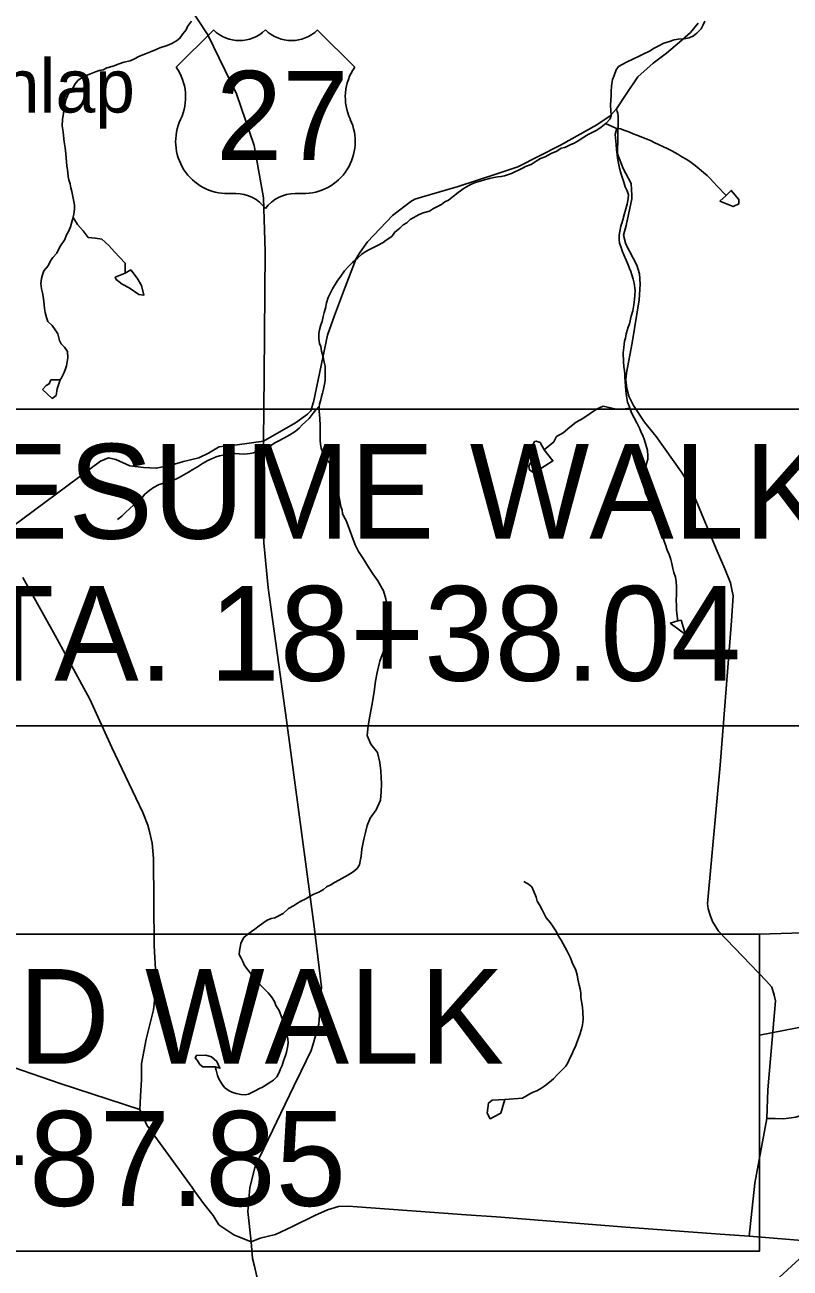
# Model space of a CAD drawing. Extents: x 0 to 69.5, y -4.5 to 22.
# Drawn here: x 3.197 to 4.328, y 18.449 to 20.286 of the extents above; entities that cross this region are included whole.
import ezdxf

# ---------------------------------------------------------------- set-up
doc = ezdxf.new("R2010")
doc.units = 0
for name, color, linetype in [('GM_X_County_Road', 7, 'Continuous'), ('GM_X_Interstate_Route', 7, 'Continuous'), ('GM_X_Minor_Lake', 7, 'Continuous'), ('GM_X_Minor_River', 7, 'Continuous'), ('GM_X_Township_Subdivision', 7, 'Continuous'), ('GM_X_Unincorporated_Text', 7, 'Continuous'), ('GM_X_US_Location', 7, 'Continuous'), ('GM_X_US_Route', 7, 'Continuous'), ('GM_X_US_Shield', 7, 'Continuous'), ('RD_P_Text', 7, 'Continuous'), ('SH_Masking', 7, 'Continuous')]:
    doc.layers.add(name, color=color, linetype=linetype)

msp = doc.modelspace()

# ---------------------------------------------------------------- linework, layer by layer
at = {"layer": 'GM_X_County_Road'}
for points in [[(3.6227, 19.7258), (3.6227, 19.726), (3.6236, 19.7286), (3.6444, 19.8276), (3.6547, 19.8565), (3.6676, 19.8922), (3.6865, 19.941), (3.6925, 19.9503), (3.7032, 19.9652), (3.7404, 20.0044), (3.7672, 20.0252), (3.7733, 20.0284), (3.7829, 20.0312), (3.8372, 20.0474), (3.8946, 20.0658), (3.9253, 20.0763), (3.9884, 20.1085), (4.042, 20.1385), (4.0618, 20.1515), (4.0712, 20.1619), (4.0855, 20.1835), (4.1029, 20.2092), (4.1255, 20.2294), (4.1453, 20.244), (4.1644, 20.2605), (4.1808, 20.2748), (4.1918, 20.2886)], [(4.2756, 18.5744), (4.2756, 18.5744), (4.2936, 18.6699), (4.295, 18.7124), (4.3061, 18.8442), (4.3043, 18.8525), (4.3007, 18.8642), (4.293, 18.8729), (4.2221, 18.9469), (4.213, 18.9612), (4.2095, 18.9706), (4.2067, 18.98), (4.2055, 18.9879), (4.2243, 19.1921), (4.2412, 19.4056), (4.2436, 19.4423), (4.2418, 19.4517), (4.2396, 19.4616), (4.2311, 19.4823), (4.2187, 19.5116), (4.1858, 19.59), (4.1779, 19.6079), (4.1675, 19.6252), (4.13, 19.6778), (4.1128, 19.6988), (4.0962, 19.7236), (4.0896, 19.7375), (4.0865, 19.7488), (4.0849, 19.7616), (4.086, 19.7721), (4.0945, 19.816), (4.1045, 19.8797), (4.1062, 19.9028), (4.1051, 19.9183), (4.1013, 19.931), (4.0851, 19.9622), (4.0818, 19.9754), (4.0855, 19.9896), (4.0939, 20.0289), (4.094, 20.0339), (4.0927, 20.0517), (4.081, 20.0738), (4.0728, 20.0957), (4.0739, 20.1462), (4.0735, 20.1512), (4.0731, 20.1549), (4.0723, 20.1581), (4.0712, 20.1619)], [(3.4832, 19.6621), (3.4839, 19.6626), (3.4954, 19.6641), (3.5106, 19.6656), (3.5494, 19.6707), (3.5969, 19.6979), (3.6147, 19.7107), (3.6194, 19.7155), (3.6227, 19.7258)], [(3.1615, 19.5318), (3.309, 19.6416), (3.3205, 19.6464), (3.3314, 19.644), (3.3523, 19.6343), (3.3723, 19.6322), (3.3912, 19.6308), (3.413, 19.6354), (3.4316, 19.6411), (3.4543, 19.6464), (3.4685, 19.6532), (3.4832, 19.6621)], [(3.3681, 18.7033), (3.3694, 18.7279), (3.3694, 18.7508), (3.3762, 18.7873), (3.3873, 18.8307), (3.3907, 18.8629), (3.3907, 18.8818), (3.3883, 18.9253), (3.3873, 19.0544), (3.3851, 19.0768), (3.3813, 19.0942), (3.3785, 19.1034), (3.3715, 19.1221), (3.3255, 19.2182), (3.2928, 19.2899), (3.2419, 19.3837), (3.194, 19.4694)], [(2.3226, 19.2206), (2.3768, 19.1884), (2.4348, 19.1381), (2.4542, 19.1116), (2.5273, 19.0205), (2.5349, 19.0104), (2.5546, 18.9972), (2.5951, 18.9816), (2.6698, 18.9569), (2.6833, 18.9516), (2.7119, 18.9461), (2.7624, 18.9381), (2.7782, 18.9339), (2.7928, 18.9251), (2.8077, 18.9174), (2.8446, 18.8965), (2.9426, 18.8282), (2.9622, 18.8128), (2.9768, 18.8059), (3.002, 18.8002), (3.1515, 18.7554), (3.2494, 18.722), (3.3671, 18.6835)], [(3.4483, 18.5622), (3.4441, 18.568), (3.3772, 18.6604), (3.3671, 18.6835), (3.3681, 18.7033)], [(4.2674, 18.4962), (4.2756, 18.5744)], [(3.5314, 18.4877), (3.5056, 18.4981), (3.4834, 18.5132), (3.4753, 18.5266), (3.4615, 18.5439), (3.4483, 18.5622)], [(3.5314, 18.4877), (3.5447, 18.4933), (3.5672, 18.4989), (3.5917, 18.5101), (3.6253, 18.5269), (3.6442, 18.5353), (3.6603, 18.5402), (3.6746, 18.5404), (3.8492, 18.5279), (3.8937, 18.5247), (4.085, 18.5097), (4.2173, 18.4999), (4.2176, 18.4999)], [(4.2176, 18.4999), (4.2674, 18.4962), (4.3632, 18.4884), (4.3722, 18.4877), (4.3808, 18.4871)]]:
    msp.add_lwpolyline(points, dxfattribs=at)
at = {"layer": 'GM_X_Interstate_Route'}
msp.add_lwpolyline([(3.7943, 18.0368), (3.8382, 18.0704), (3.8558, 18.0839), (4.1317, 18.2944), (4.2208, 18.3608), (4.3, 18.4242), (4.3415, 18.4627), (4.3632, 18.4884), (4.3688, 18.4966)], dxfattribs=at)
at = {"layer": 'GM_X_Minor_Lake'}
for p, q in [((3.9585, 19.6691), (3.9645, 19.6582)), ((4.1503, 19.4022), (4.1618, 19.4052)), ((3.4601, 18.7462), (3.4783, 18.7464)), ((3.9002, 18.6781), (3.9064, 18.6983))]:
    msp.add_line(p, q, dxfattribs=at)
for points in [[(3.3653, 19.8876), (3.3511, 19.8977), (3.3406, 19.9029), (3.332, 19.9099), (3.3305, 19.913), (3.3454, 19.9192)], [(3.3454, 19.9192), (3.3535, 19.9239), (3.3631, 19.9116), (3.3694, 19.9008), (3.3729, 19.8867), (3.3653, 19.8876)], [(3.2494, 19.7614), (3.2447, 19.7483), (3.2433, 19.7384), (3.2372, 19.734), (3.223, 19.7472)], [(3.223, 19.7472), (3.2284, 19.7532), (3.2327, 19.7558), (3.2354, 19.7614), (3.2494, 19.7614)], [(3.9645, 19.6582), (3.9774, 19.6417), (3.9523, 19.6259), (3.9477, 19.6249), (3.9425, 19.6284), (3.9418, 19.6333), (3.9458, 19.642), (3.9468, 19.6538), (3.9458, 19.661), (3.9502, 19.6704), (3.9525, 19.6707), (3.9585, 19.6691)], [(4.1618, 19.4052), (4.1667, 19.4064), (4.1731, 19.3854), (4.1503, 19.4022)], [(3.4783, 18.7464), (3.4851, 18.7444), (3.4808, 18.7543), (3.4729, 18.7613), (3.4646, 18.7638), (3.4506, 18.7633), (3.4486, 18.7595), (3.4515, 18.7561), (3.4556, 18.7499), (3.4601, 18.7462)], [(3.9064, 18.6983), (3.8877, 18.697), (3.8819, 18.6929), (3.8801, 18.6778), (3.8845, 18.6697), (3.891, 18.673), (3.9002, 18.6781)]]:
    msp.add_lwpolyline(points, dxfattribs=at)
at = {"layer": 'GM_X_Minor_River'}
msp.add_line((4.2238, 20.0255), (4.2334, 20.0338), dxfattribs=at)
for points in [[(3.4432, 20.2917), (3.4374, 20.2835), (3.4354, 20.2786), (3.4303, 20.273), (3.426, 20.2662), (3.421, 20.2625), (3.4144, 20.2584), (3.4072, 20.2555), (3.3965, 20.2519), (3.3911, 20.2498), (3.3827, 20.2461), (3.3754, 20.2432), (3.3662, 20.24), (3.3578, 20.2352), (3.3524, 20.2331), (3.3433, 20.231), (3.3364, 20.2284), (3.3276, 20.2248), (3.3181, 20.2223), (3.3127, 20.2198), (3.307, 20.2187), (3.3012, 20.2166), (3.2917, 20.2126), (3.2836, 20.2097), (3.2752, 20.2038), (3.2713, 20.1989), (3.2685, 20.1933), (3.2623, 20.1862), (3.2599, 20.1813), (3.2575, 20.1752), (3.255, 20.1635), (3.2541, 20.1555), (3.2528, 20.1464), (3.2522, 20.1369), (3.2535, 20.1282), (3.2542, 20.1228), (3.2551, 20.1133), (3.2565, 20.1045), (3.2574, 20.0957), (3.2583, 20.0843), (3.2589, 20.0771), (3.26, 20.0721), (3.2609, 20.0618), (3.2619, 20.0569), (3.2641, 20.0511), (3.2651, 20.0454), (3.2665, 20.0397), (3.2693, 20.0252), (3.2703, 20.0194), (3.2702, 20.0137), (3.2693, 20.0065), (3.2676, 19.9982), (3.2643, 19.9876), (3.2615, 19.9808), (3.2584, 19.9759), (3.256, 19.9687), (3.2489, 19.9582), (3.2442, 19.9488), (3.2384, 19.9421), (3.2348, 19.9372), (3.2313, 19.9301), (3.2251, 19.9226), (3.223, 19.9169)], [(4.202, 20.2917), (4.1988, 20.285), (4.1961, 20.2804), (4.1899, 20.2737), (4.1849, 20.2696), (4.1787, 20.2667), (4.1711, 20.2654), (4.1624, 20.2648), (4.1563, 20.2637), (4.1494, 20.2616), (4.141, 20.2591), (4.1318, 20.254), (4.1268, 20.2518), (4.1199, 20.247), (4.1114, 20.243), (4.1045, 20.2397), (4.0965, 20.236), (4.0858, 20.2309), (4.0804, 20.228), (4.0742, 20.2243), (4.0707, 20.2198), (4.0679, 20.2111), (4.0655, 20.2055), (4.0642, 20.1994), (4.0638, 20.1949), (4.0633, 20.188), (4.0635, 20.1815), (4.063, 20.1751), (4.0625, 20.1671), (4.0633, 20.1523), (4.062, 20.147), (4.0558, 20.141), (4.0485, 20.1347), (4.042, 20.1306), (4.0362, 20.1277), (4.0293, 20.124), (4.0205, 20.1185), (4.0155, 20.1152), (4.0086, 20.1111), (4.0028, 20.1086), (3.9948, 20.1049), (3.9894, 20.1039), (3.9829, 20.0995), (3.9745, 20.0958), (3.966, 20.0911), (3.9588, 20.0886), (3.9526, 20.0845), (3.9449, 20.0797), (3.9369, 20.0768), (3.9323, 20.0743), (3.9265, 20.0713), (3.9212, 20.0688), (3.9162, 20.0662), (3.9101, 20.0644), (3.9055, 20.063), (3.9009, 20.0619), (3.8959, 20.0613), (3.8902, 20.0603), (3.8834, 20.0589), (3.8761, 20.0571), (3.8696, 20.0553), (3.8631, 20.0532), (3.8578, 20.051), (3.8532, 20.0488), (3.8459, 20.0448), (3.8374, 20.0385), (3.8305, 20.0329), (3.8231, 20.027), (3.8174, 20.0244), (3.8128, 20.0207), (3.8009, 20.0149), (3.7947, 20.0108), (3.7856, 20.0083), (3.7787, 20.0051), (3.7717, 20.0014), (3.7664, 19.9985), (3.7613, 19.9936), (3.756, 19.9907), (3.7509, 19.9858), (3.7436, 19.9799), (3.7393, 19.9735), (3.7308, 19.968), (3.7262, 19.9647), (3.7181, 19.9599), (3.7124, 19.9569), (3.7063, 19.954)], [(4.0551, 20.1404), (4.0701, 20.1335), (4.0769, 20.1322), (4.0837, 20.1298), (4.0894, 20.1282), (4.0961, 20.125), (4.1014, 20.123), (4.115, 20.1174), (4.1214, 20.115), (4.1281, 20.1118), (4.1334, 20.1094), (4.1398, 20.1062), (4.1469, 20.103), (4.1529, 20.0999), (4.1575, 20.0975), (4.162, 20.0948), (4.168, 20.0912), (4.1751, 20.0873), (4.1818, 20.0826), (4.1874, 20.0783), (4.1934, 20.0732), (4.1997, 20.0678), (4.205, 20.0635), (4.2098, 20.0588), (4.2146, 20.0538), (4.2202, 20.0476), (4.2334, 20.0338)], [(4.0719, 20.1332), (4.0695, 20.124), (4.0708, 20.1095), (4.0714, 20.1015), (4.072, 20.0943), (4.0726, 20.0893), (4.074, 20.0817), (4.0758, 20.0744), (4.0779, 20.0656), (4.0807, 20.058), (4.0822, 20.0534), (4.0839, 20.0469), (4.0872, 20.0407), (4.089, 20.035), (4.0885, 20.0293), (4.0868, 20.0213), (4.0848, 20.0141), (4.0831, 20.0073), (4.0807, 19.9979), (4.079, 19.993), (4.0778, 19.9884), (4.0761, 19.9809), (4.0753, 19.9752), (4.0751, 19.9695), (4.0758, 19.9637), (4.0779, 19.9569), (4.0797, 19.9519), (4.0823, 19.9461), (4.0855, 19.9384), (4.0884, 19.9315), (4.0906, 19.9262), (4.0924, 19.9216), (4.0938, 19.9166), (4.096, 19.9105), (4.0974, 19.9044), (4.0987, 19.8937), (4.0985, 19.8865), (4.098, 19.88), (4.0967, 19.8724), (4.0954, 19.8637), (4.093, 19.8558), (4.0905, 19.8444), (4.0885, 19.8395), (4.0872, 19.8346), (4.0856, 19.8293), (4.0843, 19.8232), (4.0831, 19.8187), (4.0826, 19.8141), (4.0821, 19.8092), (4.0812, 19.8012), (4.0817, 19.7883), (4.0823, 19.781), (4.083, 19.7746), (4.0833, 19.77), (4.0835, 19.765), (4.0838, 19.7593), (4.0844, 19.7521), (4.085, 19.7452), (4.086, 19.7376), (4.0877, 19.7285), (4.0899, 19.7227), (4.0935, 19.7127), (4.0975, 19.7054), (4.1011, 19.6978), (4.1055, 19.6889), (4.1077, 19.6839), (4.1099, 19.6793), (4.1128, 19.6724), (4.1153, 19.664), (4.117, 19.6571), (4.1176, 19.6491), (4.1175, 19.6442), (4.1163, 19.6393), (4.1146, 19.6328), (4.1134, 19.6279), (4.1117, 19.6188), (4.1116, 19.6131), (4.1118, 19.6063), (4.1125, 19.6017), (4.1142, 19.594), (4.1168, 19.5883), (4.1189, 19.5829), (4.1203, 19.5776), (4.1221, 19.5711), (4.1272, 19.5596), (4.1312, 19.5526), (4.133, 19.5469), (4.1359, 19.5396), (4.1434, 19.5178), (4.1463, 19.5101), (4.1492, 19.5036), (4.1513, 19.4963), (4.1531, 19.4902), (4.1545, 19.4829), (4.1559, 19.4768), (4.1584, 19.4699), (4.1594, 19.4634), (4.16, 19.4551), (4.1598, 19.4437), (4.1596, 19.4361), (4.1598, 19.4281)], [(4.2334, 20.0338), (4.2409, 20.0414), (4.252, 20.0279), (4.2519, 20.0215), (4.2434, 20.0175), (4.2238, 20.0255)], [(3.2683, 20.0016), (3.275, 19.991), (3.2833, 19.9815), (3.2905, 19.972), (3.3012, 19.9708), (3.3107, 19.9696), (3.3213, 19.9601), (3.3296, 19.9506), (3.345, 19.9338), (3.345, 19.9264), (3.3454, 19.9192)], [(3.7063, 19.954), (3.6997, 19.9507), (3.6947, 19.947), (3.6889, 19.9418), (3.6812, 19.9347), (3.6742, 19.928), (3.6692, 19.9228), (3.6641, 19.9149), (3.6586, 19.9071), (3.6516, 19.8958), (3.6476, 19.8883), (3.6452, 19.883), (3.6428, 19.8754), (3.6411, 19.8675), (3.6391, 19.861), (3.6378, 19.855), (3.6362, 19.8478), (3.6345, 19.8429), (3.6325, 19.8353), (3.6312, 19.83), (3.6315, 19.8224), (3.6325, 19.8152), (3.6343, 19.8106), (3.6353, 19.8041), (3.6374, 19.7972), (3.6385, 19.7926), (3.6395, 19.7876), (3.6405, 19.7815), (3.6408, 19.777), (3.6406, 19.7659), (3.6408, 19.7606), (3.64, 19.7553), (3.6383, 19.7477), (3.6367, 19.742), (3.6354, 19.7367), (3.6342, 19.7318), (3.6325, 19.7254), (3.6317, 19.7205), (3.632, 19.7155), (3.6326, 19.7094), (3.6329, 19.7048), (3.6334, 19.6934), (3.6333, 19.6866), (3.6335, 19.6794), (3.6333, 19.6717), (3.634, 19.6664), (3.635, 19.6607), (3.6375, 19.6538), (3.6412, 19.6472), (3.6453, 19.6415), (3.6497, 19.6357), (3.6545, 19.6302), (3.6578, 19.6249), (3.6588, 19.6176), (3.6594, 19.6089), (3.6592, 19.6012), (3.6602, 19.5921), (3.6612, 19.5875), (3.6623, 19.5826), (3.664, 19.5745), (3.6658, 19.5688), (3.6665, 19.5642), (3.669, 19.5588), (3.6716, 19.5538)], [(3.223, 19.9169), (3.2218, 19.9112), (3.2205, 19.9037), (3.2215, 19.896), (3.2229, 19.8899), (3.2239, 19.8846), (3.2249, 19.8773), (3.2258, 19.867), (3.2272, 19.8609), (3.229, 19.8537), (3.2311, 19.8479), (3.2371, 19.8417), (3.2419, 19.8355), (3.2456, 19.8294), (3.248, 19.8198), (3.2506, 19.8148), (3.2554, 19.8098), (3.2598, 19.8036), (3.2604, 19.7941), (3.2595, 19.788), (3.2583, 19.782), (3.2566, 19.7763), (3.2539, 19.7703), (3.2511, 19.7646), (3.2494, 19.7614)], [(3.6321, 19.7227), (3.627, 19.7171), (3.6228, 19.7123), (3.6173, 19.7044), (3.6115, 19.6996), (3.6069, 19.6951), (3.6022, 19.6902), (3.5964, 19.6854), (3.5887, 19.6802), (3.5799, 19.6755), (3.5715, 19.6711), (3.5665, 19.6685), (3.5615, 19.6648), (3.5561, 19.6611), (3.5503, 19.6578), (3.5438, 19.6564), (3.535, 19.6539), (3.5301, 19.6529), (3.5255, 19.6522), (3.5202, 19.6516), (3.5138, 19.6521), (3.5077, 19.6526), (3.5005, 19.6527), (3.4951, 19.6517), (3.4898, 19.6503), (3.4848, 19.6492), (3.4799, 19.6478), (3.4753, 19.646), (3.4672, 19.6424), (3.4596, 19.638), (3.4523, 19.6332), (3.4453, 19.6291), (3.4388, 19.6251), (3.4319, 19.621), (3.425, 19.6173), (3.42, 19.6148), (3.4146, 19.613), (3.4101, 19.6119), (3.4005, 19.6083), (3.3955, 19.6069), (3.3871, 19.6025), (3.3817, 19.5984), (3.3744, 19.5925), (3.3709, 19.588), (3.3631, 19.5817), (3.3573, 19.5765), (3.3519, 19.5713), (3.3457, 19.5657), (3.3403, 19.5601), (3.3341, 19.5553)], [(4.0909, 19.7198), (4.0805, 19.7184), (4.0709, 19.7184), (4.0515, 19.7227), (4.0419, 19.7184), (4.0322, 19.712), (4.0214, 19.7044), (4.0118, 19.6991), (4.0021, 19.6916), (3.9924, 19.683), (3.9828, 19.6776), (3.9785, 19.6701), (3.9645, 19.6582)], [(3.6716, 19.5538), (3.6851, 19.5177), (3.6902, 19.5081), (3.6967, 19.4973), (3.7048, 19.4845), (3.711, 19.4749), (3.7187, 19.4644), (3.7271, 19.4498), (3.7302, 19.4379), (3.7322, 19.4249), (3.7322, 19.4097), (3.7311, 19.396), (3.7308, 19.3831), (3.7298, 19.3717), (3.7264, 19.3589), (3.7215, 19.3457), (3.7174, 19.3291), (3.7151, 19.3162), (3.7133, 19.301), (3.7106, 19.2859), (3.7088, 19.2749), (3.7067, 19.2647), (3.7041, 19.2503), (3.703, 19.2362), (3.708, 19.2232), (3.7183, 19.2108), (3.7217, 19.1962), (3.723, 19.184), (3.7235, 19.1741), (3.724, 19.1646), (3.7234, 19.1528), (3.7223, 19.1403), (3.7159, 19.126), (3.7072, 19.114), (3.7028, 19.1031), (3.7003, 19.0925), (3.6977, 19.0827), (3.6951, 19.0679), (3.6937, 19.0577)], [(4.1598, 19.4281), (4.1601, 19.4212), (4.161, 19.4121), (4.1618, 19.4052)], [(3.6937, 19.0577), (3.6926, 19.0502), (3.6916, 19.0449), (3.6881, 19.0397), (3.6823, 19.0348), (3.6742, 19.0297), (3.6654, 19.0249), (3.6608, 19.0223), (3.6546, 19.019), (3.6489, 19.0154), (3.6427, 19.0124), (3.6381, 19.0087), (3.6316, 19.0047), (3.6239, 19.0018), (3.6185, 18.9985), (3.6112, 18.9944), (3.6047, 18.9911), (3.5986, 18.9871), (3.594, 18.9845), (3.5867, 18.9805), (3.5785, 18.973), (3.5663, 18.9668), (3.5609, 18.9654), (3.5552, 18.9632), (3.5502, 18.9595), (3.5432, 18.9547), (3.5367, 18.9499), (3.5321, 18.9466), (3.5267, 18.9425), (3.5205, 18.9377), (3.5181, 18.9332), (3.5161, 18.9286), (3.5149, 18.9233), (3.514, 18.9176), (3.5139, 18.9123), (3.5168, 18.9069), (3.519, 18.9023), (3.5216, 18.8962), (3.5264, 18.8896), (3.5319, 18.8831), (3.5386, 18.8749), (3.5441, 18.868), (3.5505, 18.8618), (3.5564, 18.8556), (3.5612, 18.8501), (3.566, 18.8432), (3.5678, 18.8371), (3.5726, 18.8297), (3.5762, 18.8205), (3.5787, 18.8148), (3.5813, 18.8098), (3.5823, 18.8052), (3.5841, 18.7987), (3.5847, 18.7922), (3.5858, 18.7876), (3.586, 18.7819), (3.5852, 18.7751), (3.5835, 18.7679), (3.5819, 18.763), (3.5794, 18.7551), (3.577, 18.7486), (3.5746, 18.7434), (3.573, 18.7381), (3.5691, 18.7317), (3.5644, 18.7268), (3.5579, 18.7228), (3.5533, 18.7195), (3.5479, 18.7165), (3.5429, 18.714), (3.5383, 18.7114), (3.5276, 18.7063), (3.5226, 18.7052), (3.5162, 18.7057), (3.509, 18.707), (3.5045, 18.7083), (3.4988, 18.711), (3.4921, 18.7161), (3.488, 18.7211), (3.4836, 18.7285), (3.4818, 18.7338), (3.4797, 18.7415), (3.4783, 18.7464)], [(3.9344, 19.0203), (3.9412, 19.0163), (3.946, 19.0124), (3.9489, 19.0055), (3.9525, 18.9971), (3.9539, 18.9914), (3.9573, 18.986), (3.9613, 18.9783), (3.9671, 18.9668), (3.9738, 18.959), (3.9815, 18.9475), (3.9867, 18.9382), (3.9896, 18.9336), (3.9984, 18.9174), (4.0009, 18.9125), (4.0031, 18.9075), (4.0056, 18.9006), (4.0111, 18.8894), (4.0132, 18.8822), (4.0142, 18.8761), (4.0163, 18.8673), (4.0174, 18.8615), (4.0184, 18.8554), (4.0186, 18.8493), (4.0196, 18.8429), (4.021, 18.8345), (4.0216, 18.8276), (4.0221, 18.8162), (4.0212, 18.8086), (4.0196, 18.8022), (4.0171, 18.7942), (4.0151, 18.7886), (4.0123, 18.781), (4.0107, 18.7765), (4.0079, 18.7712), (4.0055, 18.7655), (4.0024, 18.7591), (4, 18.7531), (3.9964, 18.7475), (3.9903, 18.7415), (3.9837, 18.7348), (3.9782, 18.7288), (3.9724, 18.724), (3.9651, 18.7184), (3.9593, 18.7144), (3.9536, 18.7111), (3.9482, 18.7089), (3.9432, 18.7067), (3.9382, 18.7034), (3.9325, 18.7001)], [(3.9325, 18.7001), (3.9064, 18.6983)]]:
    msp.add_lwpolyline(points, dxfattribs=at)
at = {"layer": 'GM_X_Township_Subdivision'}
msp.add_lwpolyline([(4.2936, 18.6699), (4.3057, 18.6699), (4.3184, 18.6696), (4.3364, 18.6722), (4.3581, 18.6795), (4.3823, 18.6925), (4.3989, 18.7082), (4.4101, 18.7223), (4.4273, 18.7533), (4.4544, 18.8124), (4.4896, 18.8803), (4.5167, 18.9255), (4.5538, 18.9777)], dxfattribs=at)
at = {"layer": 'GM_X_US_Route'}
for points in [[(3.6051, 18.7398), (3.6201, 18.7706), (3.6223, 18.7784), (3.6313, 18.8094), (3.6351, 18.8644), (3.6245, 18.9536), (3.5834, 19.2587), (3.5563, 19.4543), (3.55, 19.5209), (3.5474, 19.5807), (3.5494, 19.6707), (3.5507, 19.7683), (3.5521, 19.951), (3.5496, 20.0305), (3.536, 20.108), (3.5099, 20.1843), (3.4674, 20.2712), (3.4379, 20.3161), (3.4128, 20.344), (3.3554, 20.3968), (3.2808, 20.4535), (3.2774, 20.4561), (3.2078, 20.5124)], [(3.5314, 18.4877), (3.5267, 18.5328), (3.5295, 18.568), (3.5372, 18.5994), (3.5945, 18.718), (3.6051, 18.7398)], [(3.5362, 18.452), (3.5335, 18.4631), (3.5314, 18.4877)], [(3.5606, 18.3842), (3.5504, 18.4078), (3.5398, 18.4365), (3.5362, 18.452)]]:
    msp.add_lwpolyline(points, dxfattribs=at)
at = {"layer": 'GM_X_US_Shield'}
for p, q in [((3.4756, 20.2784), (3.4207, 20.2235)), ((3.6844, 20.2235), (3.6294, 20.2784)), ((3.4976, 20.0367), (3.5086, 20.0367)), ((3.5965, 20.0367), (3.6075, 20.0367))]:
    msp.add_line(p, q, dxfattribs=at)
for centre, radius, start, end in [((3.5141, 20.3177), 0.0549, 225.573, 314.427), ((3.591, 20.3177), 0.0549, 225.573, 314.427), ((3.3577, 20.1794), 0.0769, 334.5471, 35.0009), ((3.7474, 20.1794), 0.0769, 144.9991, 205.4529), ((3.4967, 20.1136), 0.0769, 154.8319, 270.6383), ((3.6083, 20.1136), 0.0769, 269.3617, 25.1681), ((3.5086, 19.9818), 0.0549, 36.8699, 90), ((3.5965, 19.9818), 0.0549, 90, 143.1301)]:
    msp.add_arc(centre, radius, start, end, dxfattribs=at)
at = {"layer": 'RD_P_Text'}
for points in [[(2.9371, 19.7183), (4.8665, 19.7183), (4.8665, 19.2501), (2.9371, 19.2501)], [(2.3533, 18.9424), (4.2827, 18.9424), (4.2827, 18.4742), (2.3533, 18.4742)]]:
    msp.add_lwpolyline(points, close=True, dxfattribs=at)
msp.add_lwpolyline([(4.2827, 18.7932), (5.1946, 18.9704), (4.2827, 18.9424), (4.2827, 18.7932)], dxfattribs=at)
at = {"layer": 'SH_Masking'}
for points in [[(4.8665, 19.7183), (2.9371, 19.7183), (2.9371, 19.2501), (4.8665, 19.2501)], [(4.2827, 18.9424), (2.3533, 18.9424), (2.3533, 18.4742), (4.2827, 18.4742)]]:
    msp.add_lwpolyline(points, close=True, dxfattribs=at)

# ---------------------------------------------------------------- texts
at = {"layer": 'GM_X_Unincorporated_Text'}
msp.add_text('Dunlap', height=0.07898, rotation=0, dxfattribs=at).set_placement((3.025, 20.1565))
at = {"layer": 'GM_X_US_Location'}
for s in ['0', '/']:
    msp.add_text(s, height=0.000189, dxfattribs=at).set_placement((3.5525, 20.151))
msp.add_text('27', height=0.000189, rotation=0, dxfattribs=at).set_placement((3.5134, 20.1118))
at = {"layer": 'GM_X_US_Shield'}
msp.add_text('27', height=0.13184, dxfattribs=at).set_placement((3.4792, 20.0862))
at = {"layer": 'RD_P_Text'}
for s, p in [('RESUME WALK', (3.0013, 19.5269)), ('STA. 18+38.04', (3.0013, 19.3169)), ('SUSPEND WALK', (2.4175, 18.751)), ('STA. 17+87.85', (2.4175, 18.541))]:
    msp.add_text(s, height=0.14, dxfattribs=at).set_placement(p)

doc.saveas('drawing.dxf')
